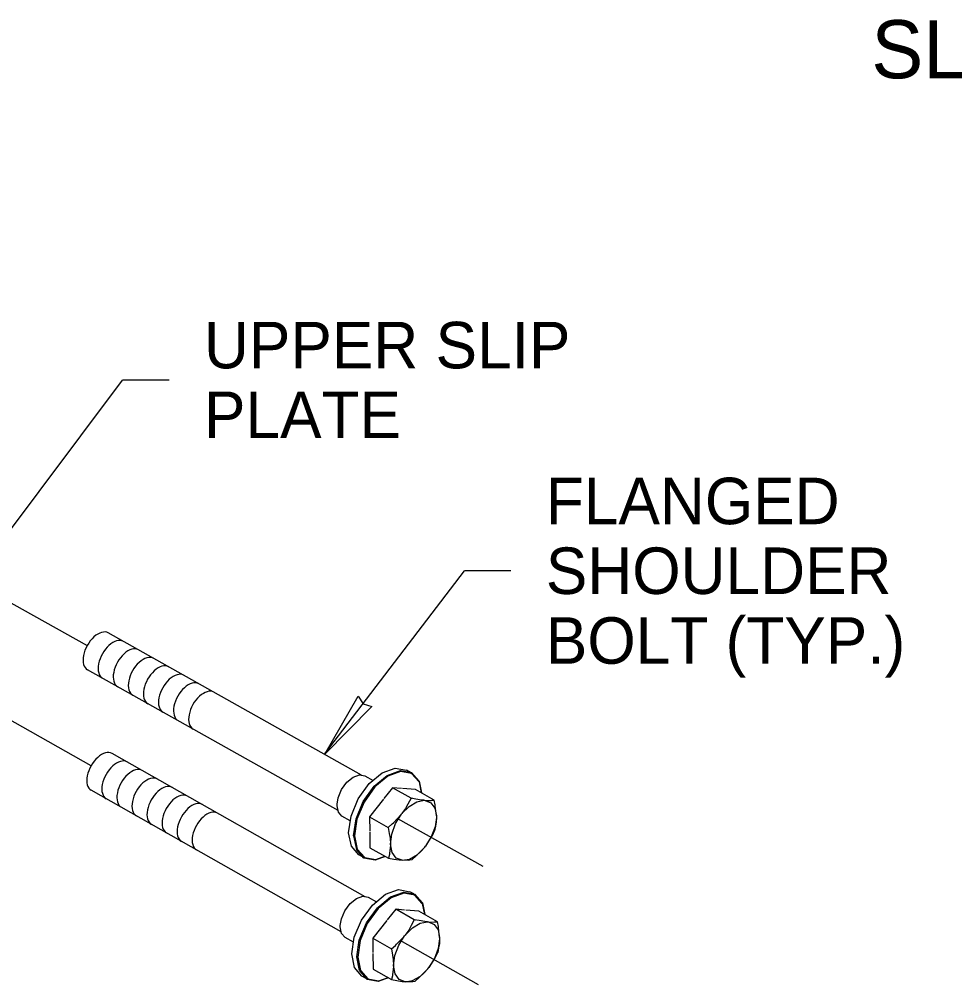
# Model space of a CAD drawing. Extents: x 99862 to 103151, y 99997 to 117076.
# Drawn here: x 100516.7 to 100838.4, y 116205.8 to 116537.9 of the extents above; entities that cross this region are included whole.
import ezdxf

# ---------------------------------------------------------------- set-up
doc = ezdxf.new("R2010")
doc.units = 0
for name, color, linetype in [('Level 13', 7, 'Continuous'), ('Level 15', 7, 'Continuous'), ('Level 20', 7, 'Continuous'), ('Level 3', 7, 'Continuous'), ('Level 5', 7, 'Continuous'), ('Level 9', 7, 'Continuous')]:
    doc.layers.add(name, color=color, linetype=linetype)

msp = doc.modelspace()

# ---------------------------------------------------------------- linework, layer by layer
at = {"layer": 'Level 13'}
for p, q in [((100634.43, 116277.84), (100547.3, 116326.79)), ((100626.33, 116265.69), (100540.17, 116314.09)), ((100635.71, 116236.02), (100548.61, 116285.34)), ((100627.38, 116224), (100541.44, 116272.66))]:
    msp.add_line(p, q, dxfattribs=at)
for centre, major_axis, start_param, end_param in [((100543.74, 116320.44), (3.57, 6.35), 6.283173, 9.424785), ((100548.92, 116317.52), (3.57, 6.35), 6.283174, 9.424783), ((100554.11, 116314.61), (3.57, 6.35), 6.283172, 9.424785), ((100559.3, 116311.69), (3.57, 6.35), 6.283179, 9.424784), ((100564.49, 116308.78), (3.57, 6.35), 6.283177, 9.424782), ((100569.68, 116305.87), (3.57, 6.35), 6.283174, 9.424785), ((100574.86, 116302.95), (3.57, 6.35), 6.283176, 9.424783), ((100580.05, 116300.04), (3.57, 6.35), 6.283178, 9.42478), ((100545.02, 116279), (3.59, 6.34), 6.283173, 9.424785), ((100550.2, 116276.06), (3.59, 6.34), 6.283174, 9.424783), ((100555.38, 116273.13), (3.59, 6.34), 6.283172, 9.424785), ((100560.56, 116270.2), (3.59, 6.34), 6.283179, 9.424784), ((100565.74, 116267.27), (3.59, 6.34), 6.283177, 9.424782), ((100570.92, 116264.34), (3.59, 6.34), 6.283174, 9.424785), ((100576.09, 116261.41), (3.59, 6.34), 6.283176, 9.424783), ((100581.27, 116258.47), (3.59, 6.34), 6.283178, 9.42478)]:
    msp.add_ellipse(centre, major_axis=major_axis, ratio=0.57735, start_param=start_param, end_param=end_param, dxfattribs=at)
at = {"layer": 'Level 15'}
for p, q in [((100494.27, 116336.4), (100552.22, 116413.78)), ((100568.22, 116413.78), (100552.22, 116413.78)), ((100541.36, 116281.07), (100404.94, 116358.17)), ((100621.65, 116285.02), (100669.82, 116348.17)), ((100685.82, 116348.17), (100669.82, 116348.17)), ((100674.59, 116205.77), (100647.7, 116220.97))]:
    msp.add_line(p, q, dxfattribs=at)
for points in [[(100405.01, 116397.92), (100540.07, 116322.5)], [(100646.76, 116262.92), (100676.13, 116246.51)]]:
    msp.add_lwpolyline(points, dxfattribs=at)
msp.add_lwpolyline([(100621.75, 116285.09), (100633.22, 116305.06), (100634.95, 116302.41), (100637.97, 116301.44)], close=True, dxfattribs=at)
at = {"layer": 'Level 3'}
for p, q in [((100643.41, 116277.4), (100643.41, 116277.46)), ((100647.83, 116279.02), (100647.84, 116279.08)), ((100651.59, 116278.34), (100651.63, 116278.4)), ((100654.18, 116275.52), (100651.63, 116278.4)), ((100639.02, 116273.74), (100639, 116273.78)), ((100654.21, 116275.78), (100655.03, 116271.73)), ((100651.84, 116269.82), (100651.74, 116269.78)), ((100635.32, 116268.58), (100635.29, 116268.6)), ((100632.88, 116262.72), (100632.84, 116262.71)), ((100631.69, 116256.98), (100632.65, 116252.27)), ((100635.25, 116249.34), (100632.65, 116252.27)), ((100635.54, 116249.55), (100635.51, 116249.49)), ((100639.31, 116248.87), (100639.3, 116248.81)), ((100648.98, 116237.23), (100648.99, 116237.29)), ((100652.74, 116236.54), (100652.77, 116236.6)), ((100655.32, 116233.71), (100652.77, 116236.6)), ((100644.55, 116235.63), (100644.55, 116235.68)), ((100655.35, 116233.97), (100656.16, 116229.91)), ((100640.15, 116231.98), (100640.13, 116232.02)), ((100636.44, 116226.83), (100636.4, 116226.85)), ((100652.96, 116228.02), (100652.86, 116227.98)), ((100633.97, 116220.98), (100633.93, 116220.97)), ((100633.14, 116215.31), (100633.09, 116215.28)), ((100636.3, 116207.59), (100633.71, 116210.53)), ((100636.6, 116207.8), (100636.56, 116207.74)), ((100640.36, 116207.11), (100640.34, 116207.05))]:
    msp.add_line(p, q, dxfattribs=at)
for points in [[(100638.79, 116274.01), (100643.27, 116277.75), (100643.27, 116277.75)], [(100643.42, 116277.41), (100643.41, 116277.46), (100639, 116273.78)], [(100643.27, 116277.75), (100647.77, 116279.4), (100647.77, 116279.4)], [(100647.83, 116279.02), (100647.84, 116279.08), (100643.41, 116277.46)], [(100647.77, 116279.4), (100651.62, 116278.71), (100651.62, 116278.71)], [(100651.6, 116278.34), (100651.63, 116278.4), (100647.84, 116279.08)], [(100651.62, 116278.71), (100654.21, 116275.78), (100654.21, 116275.78)], [(100635.02, 116268.75), (100638.79, 116274.01), (100638.79, 116274.01)], [(100639.03, 116273.75), (100639, 116273.78), (100635.29, 116268.6)], [(100654.14, 116275.46), (100654.18, 116275.52), (100654.94, 116271.78)], [(100632.53, 116262.77), (100635.02, 116268.75), (100635.02, 116268.75)], [(100635.33, 116268.59), (100635.29, 116268.6), (100632.84, 116262.71)], [(100631.7, 116256.98), (100631.69, 116256.98), (100632.53, 116262.77), (100632.53, 116262.77)], [(100632.88, 116262.73), (100632.84, 116262.71), (100632.02, 116257.02)], [(100632.06, 116257.06), (100632.02, 116257.02), (100632.96, 116252.37)], [(100632.96, 116252.37), (100635.51, 116249.49)], [(100642.57, 116249.92), (100639.09, 116248.65), (100639.09, 116248.65)], [(100639.3, 116248.87), (100639.3, 116248.81), (100642.48, 116249.98)], [(100639.09, 116248.65), (100635.25, 116249.34), (100635.25, 116249.34)], [(100635.54, 116249.56), (100635.51, 116249.49), (100639.3, 116248.81)], [(100644.41, 116235.98), (100648.92, 116237.61), (100648.92, 116237.61)], [(100648.98, 116237.23), (100648.99, 116237.29), (100644.55, 116235.68)], [(100648.92, 116237.61), (100652.76, 116236.91), (100652.76, 116236.9)], [(100652.75, 116236.54), (100652.77, 116236.6), (100648.99, 116237.29)], [(100652.76, 116236.91), (100655.35, 116233.97), (100655.35, 116233.97)], [(100639.92, 116232.25), (100644.41, 116235.98), (100644.41, 116235.97)], [(100644.56, 116235.63), (100644.55, 116235.68), (100640.13, 116232.02)], [(100655.28, 116233.65), (100655.32, 116233.71), (100656.07, 116229.96)], [(100636.13, 116227), (100639.92, 116232.25), (100639.92, 116232.25)], [(100640.16, 116231.99), (100640.13, 116232.02), (100636.4, 116226.85)], [(100636.44, 116226.84), (100636.4, 116226.85), (100633.93, 116220.97)], [(100633.98, 116220.99), (100633.93, 116220.97), (100633.09, 116215.28)], [(100632.81, 116215.25), (100632.8, 116215.25), (100632.8, 116215.25), (100632.77, 116215.25)], [(100633.14, 116215.32), (100633.09, 116215.28), (100634.02, 116210.63)], [(100634.02, 116210.63), (100636.56, 116207.74)], [(100640.14, 116206.89), (100636.3, 116207.59), (100636.3, 116207.59)], [(100636.59, 116207.81), (100636.56, 116207.74), (100640.34, 116207.05)], [(100643.62, 116208.15), (100640.14, 116206.89), (100640.14, 116206.89)], [(100640.35, 116207.11), (100640.34, 116207.05), (100643.53, 116208.21)]]:
    msp.add_lwpolyline(points, dxfattribs=at)
at = {"layer": 'Level 5'}
for p, q in [((100651.22, 116278.78), (100649.84, 116279.55)), ((100652.37, 116236.98), (100650.99, 116237.76)), ((100633.79, 116210.56), (100633.77, 116210.58))]:
    msp.add_line(p, q, dxfattribs=at)
for points in [[(100634.98, 116249.64), (100633.5, 116250.47), (100630.91, 116253.38), (100629.96, 116258.06), (100630.79, 116263.8), (100633.28, 116269.73), (100637.04, 116274.93), (100641.51, 116278.63), (100646.01, 116280.25), (100649.84, 116279.55)], [(100630.54, 116262.11), (100627.68, 116263.72), (100626.44, 116265.11), (100625.98, 116267.35), (100625.99, 116267.91), (100626.38, 116270.1), (100627.57, 116272.94), (100629.37, 116275.43), (100631.51, 116277.2), (100633.66, 116277.97), (100635.5, 116277.64), (100638.36, 116276.03)], [(100642.58, 116249.92), (100642.56, 116249.9), (100642.27, 116249.81)], [(100636.03, 116207.89), (100634.56, 116208.73), (100631.97, 116211.65), (100631.04, 116216.33), (100631.89, 116222.07), (100634.39, 116227.99), (100638.18, 116233.18), (100642.66, 116236.86), (100647.16, 116238.47), (100650.99, 116237.76)], [(100631.64, 116220.38), (100628.77, 116222), (100627.54, 116223.39), (100627.09, 116225.64), (100627.1, 116226.19), (100627.5, 116228.38), (100628.7, 116231.21), (100630.51, 116233.7), (100632.65, 116235.46), (100634.81, 116236.23), (100636.64, 116235.89), (100639.5, 116234.27)], [(100633.68, 116210.68), (100633.68, 116210.68), (100632.74, 116215.37), (100633.59, 116221.11), (100636.1, 116227.02), (100639.88, 116232.22), (100640.41, 116232.65)], [(100643.63, 116208.14), (100643.61, 116208.13), (100643.33, 116208.04)]]:
    msp.add_lwpolyline(points, dxfattribs=at)
at = {"layer": 'Level 9'}
for p, q in [((100651.43, 116269.89), (100645.02, 116273.49)), ((100651.43, 116269.89), (100645.02, 116273.49)), ((100652.55, 116228.09), (100646.15, 116231.71)), ((100652.55, 116228.09), (100646.15, 116231.71))]:
    msp.add_line(p, q, dxfattribs=at)
for points in [[(100648.1, 116273.25), (100645.02, 116273.49), (100642.13, 116269.8)], [(100648.1, 116273.25), (100645.02, 116273.49), (100642.13, 116269.8)], [(100660.17, 116263.82), (100660.17, 116263.93), (100659.79, 116267.21), (100659.74, 116267.63), (100659.4, 116269.27), (100652.99, 116272.87), (100648.51, 116273.22)], [(100660.17, 116263.82), (100660.17, 116263.93), (100659.79, 116267.21), (100659.74, 116267.63), (100659.4, 116269.27), (100652.99, 116272.87), (100648.51, 116273.22)], [(100649.53, 116266.33), (100648.31, 116264.61), (100650.78, 116267.11), (100653.46, 116268.72), (100655.96, 116269.19), (100655.06, 116269.29), (100653.07, 116269.62), (100651.43, 116269.89), (100650.36, 116267.89), (100649.53, 116266.33)], [(100649.53, 116266.33), (100648.31, 116264.61), (100650.78, 116267.11), (100653.46, 116268.72), (100655.96, 116269.19), (100655.06, 116269.29), (100653.07, 116269.62), (100651.43, 116269.89), (100650.36, 116267.89), (100649.53, 116266.33)], [(100641.99, 116269.62), (100637.18, 116263.5), (100637.23, 116258.61)], [(100641.99, 116269.62), (100637.18, 116263.5), (100637.23, 116258.61)], [(100655.96, 116269.19), (100656.3, 116269.17), (100656.75, 116269.14), (100658.36, 116269.18), (100658.75, 116269.19), (100659.4, 116269.27)], [(100655.96, 116269.19), (100656.3, 116269.17), (100656.75, 116269.14), (100658.36, 116269.18), (100658.75, 116269.19), (100659.4, 116269.27)], [(100656.3, 116269.17), (100658.29, 116268.36), (100659.64, 116266.49), (100660.17, 116263.82)], [(100656.3, 116269.17), (100658.29, 116268.36), (100659.64, 116266.49), (100660.17, 116263.82)], [(100637.18, 116263.5), (100643.59, 116259.9), (100644.99, 116261.08), (100645.37, 116261.48), (100647.95, 116264.15), (100648.13, 116264.38), (100648.31, 116264.61)], [(100637.18, 116263.5), (100643.59, 116259.9), (100644.99, 116261.08), (100645.37, 116261.48), (100647.95, 116264.15), (100648.13, 116264.38), (100648.31, 116264.61)], [(100648.41, 116248.57), (100646.34, 116249.34), (100644.9, 116251.27), (100644.36, 116254.13), (100644.79, 116257.57), (100646.13, 116261.17), (100648.13, 116264.38)], [(100648.41, 116248.57), (100646.34, 116249.34), (100644.9, 116251.27), (100644.36, 116254.13), (100644.79, 116257.57), (100646.13, 116261.17), (100648.13, 116264.38)], [(100660.18, 116263.32), (100659.71, 116260.05), (100658.41, 116256.59), (100656.46, 116253.44)], [(100660.18, 116263.32), (100659.71, 116260.05), (100658.41, 116256.59), (100656.46, 116253.44)], [(100660.17, 116263.82), (100660.18, 116263.32), (100660.1, 116261.74), (100659.83, 116260.28), (100659.52, 116258.66)], [(100660.17, 116263.82), (100660.18, 116263.32), (100660.1, 116261.74), (100659.83, 116260.28), (100659.52, 116258.66)], [(100643.59, 116259.9), (100643.96, 116257.74), (100644.24, 116256.19), (100644.35, 116254.14), (100644.36, 116253.82), (100644.06, 116250.92), (100644.02, 116250.55), (100643.71, 116249.28)], [(100643.59, 116259.9), (100643.96, 116257.74), (100644.24, 116256.19), (100644.35, 116254.14), (100644.36, 116253.82), (100644.06, 116250.92), (100644.02, 116250.55), (100643.71, 116249.28)], [(100637.24, 116258.22), (100637.3, 116252.88), (100643.71, 116249.28), (100645.55, 116248.98), (100647.34, 116248.68), (100648.41, 116248.57)], [(100637.24, 116258.22), (100637.3, 116252.88), (100643.71, 116249.28), (100645.55, 116248.98), (100647.34, 116248.68), (100648.41, 116248.57)], [(100656.18, 116253.08), (100656.46, 116253.44), (100656.59, 116253.61), (100658.49, 116256.66), (100658.77, 116257.11), (100659.52, 116258.66)], [(100656.18, 116253.08), (100656.46, 116253.44), (100656.59, 116253.61), (100658.49, 116256.66), (100658.77, 116257.11), (100659.52, 116258.66)], [(100656.18, 116253.08), (100654.82, 116251.54), (100653.32, 116250.16), (100651.68, 116248.67), (100651.03, 116248.58), (100650.57, 116248.54), (100650.54, 116248.54), (100648.41, 116248.57)], [(100648.41, 116248.57), (100650.93, 116248.98), (100653.66, 116250.57), (100656.18, 116253.08)], [(100656.18, 116253.08), (100654.82, 116251.54), (100653.32, 116250.16), (100651.68, 116248.67), (100651.03, 116248.58), (100650.57, 116248.54), (100650.54, 116248.54), (100648.41, 116248.57)], [(100648.41, 116248.57), (100650.93, 116248.98), (100653.66, 116250.57), (100656.18, 116253.08)], [(100649.23, 116231.46), (100646.15, 116231.71), (100643.25, 116228.03)], [(100649.23, 116231.46), (100646.15, 116231.71), (100643.25, 116228.03)], [(100661.27, 116221.99), (100661.27, 116222.1), (100660.9, 116225.38), (100660.85, 116225.8), (100660.51, 116227.45), (100654.12, 116231.07), (100649.64, 116231.43)], [(100661.27, 116221.99), (100661.27, 116222.1), (100660.9, 116225.38), (100660.85, 116225.8), (100660.51, 116227.45), (100654.12, 116231.07), (100649.64, 116231.43)], [(100643.1, 116227.85), (100638.27, 116221.74), (100638.32, 116216.86)], [(100643.1, 116227.85), (100638.27, 116221.74), (100638.32, 116216.86)], [(100650.63, 116224.54), (100649.41, 116222.82), (100651.89, 116225.31), (100654.57, 116226.91), (100657.07, 116227.38), (100656.18, 116227.47), (100654.18, 116227.81), (100652.55, 116228.09), (100651.47, 116226.09), (100650.63, 116224.54)], [(100650.63, 116224.54), (100649.41, 116222.82), (100651.89, 116225.31), (100654.57, 116226.91), (100657.07, 116227.38), (100656.18, 116227.47), (100654.18, 116227.81), (100652.55, 116228.09), (100651.47, 116226.09), (100650.63, 116224.54)], [(100657.07, 116227.38), (100657.42, 116227.35), (100657.87, 116227.32), (100659.47, 116227.35), (100659.87, 116227.36), (100660.51, 116227.45)], [(100657.07, 116227.38), (100657.42, 116227.35), (100657.87, 116227.32), (100659.47, 116227.35), (100659.87, 116227.36), (100660.51, 116227.45)], [(100657.42, 116227.35), (100659.4, 116226.53), (100660.75, 116224.66), (100661.27, 116221.99)], [(100657.42, 116227.35), (100659.4, 116226.53), (100660.75, 116224.66), (100661.27, 116221.99)], [(100638.27, 116221.74), (100644.67, 116218.12), (100646.08, 116219.3), (100646.46, 116219.7), (100649.05, 116222.36), (100649.23, 116222.59), (100649.41, 116222.82)], [(100638.27, 116221.74), (100644.67, 116218.12), (100646.08, 116219.3), (100646.46, 116219.7), (100649.05, 116222.36), (100649.23, 116222.59), (100649.41, 116222.82)], [(100649.46, 116206.78), (100647.39, 116207.55), (100645.96, 116209.49), (100645.43, 116212.35), (100645.87, 116215.79), (100647.22, 116219.38), (100649.23, 116222.59)], [(100649.46, 116206.78), (100647.39, 116207.55), (100645.96, 116209.49), (100645.43, 116212.35), (100645.87, 116215.79), (100647.22, 116219.38), (100649.23, 116222.59)], [(100661.27, 116221.49), (100660.8, 116218.22), (100659.49, 116214.77), (100657.52, 116211.63)], [(100661.27, 116221.49), (100660.8, 116218.22), (100659.49, 116214.77), (100657.52, 116211.63)], [(100661.27, 116221.99), (100661.27, 116221.49), (100661.19, 116219.91), (100660.91, 116218.45), (100660.6, 116216.83)], [(100661.27, 116221.99), (100661.27, 116221.49), (100661.19, 116219.91), (100660.91, 116218.45), (100660.6, 116216.83)], [(100644.67, 116218.12), (100645.04, 116215.97), (100645.31, 116214.42), (100645.41, 116212.36), (100645.43, 116212.04), (100645.11, 116209.15), (100645.07, 116208.78), (100644.76, 116207.51)], [(100644.67, 116218.12), (100645.04, 116215.97), (100645.31, 116214.42), (100645.41, 116212.36), (100645.43, 116212.04), (100645.11, 116209.15), (100645.07, 116208.78), (100644.76, 116207.51)], [(100657.24, 116211.27), (100657.52, 116211.63), (100657.65, 116211.79), (100659.57, 116214.83), (100659.85, 116215.28), (100660.6, 116216.83)], [(100657.24, 116211.27), (100657.52, 116211.63), (100657.65, 116211.79), (100659.57, 116214.83), (100659.85, 116215.28), (100660.6, 116216.83)], [(100638.32, 116216.46), (100638.36, 116211.13), (100644.76, 116207.51), (100646.59, 116207.2), (100648.39, 116206.89), (100649.46, 116206.78)], [(100638.32, 116216.46), (100638.36, 116211.13), (100644.76, 116207.51), (100646.59, 116207.2), (100648.39, 116206.89), (100649.46, 116206.78)], [(100657.24, 116211.27), (100655.88, 116209.72), (100654.37, 116208.35), (100652.73, 116206.86), (100652.08, 116206.78), (100651.62, 116206.74), (100651.59, 116206.74), (100649.46, 116206.78)], [(100649.46, 116206.78), (100651.98, 116207.18), (100654.71, 116208.76), (100657.24, 116211.27)], [(100657.24, 116211.27), (100655.88, 116209.72), (100654.37, 116208.35), (100652.73, 116206.86), (100652.08, 116206.78), (100651.62, 116206.74), (100651.59, 116206.74), (100649.46, 116206.78)], [(100649.46, 116206.78), (100651.98, 116207.18), (100654.71, 116208.76), (100657.24, 116211.27)]]:
    msp.add_lwpolyline(points, dxfattribs=at)

# ---------------------------------------------------------------- texts
at = {"layer": 'Level 20'}
for s, height, p in [('SLIP PLATE DETAIL ', 20, (100809.79, 116517.56)), ('UPPER SLIP', 16, (100580.22, 116417.79)), ('PLATE', 16, (100580.22, 116393.79)), ('FLANGED', 16, (100697.81, 116364.17)), ('SHOULDER ', 16, (100697.81, 116340.17)), ('BOLT (TYP.)', 16, (100697.81, 116316.17))]:
    msp.add_text(s, height=height, dxfattribs=at).set_placement(p)

doc.saveas('drawing.dxf')
